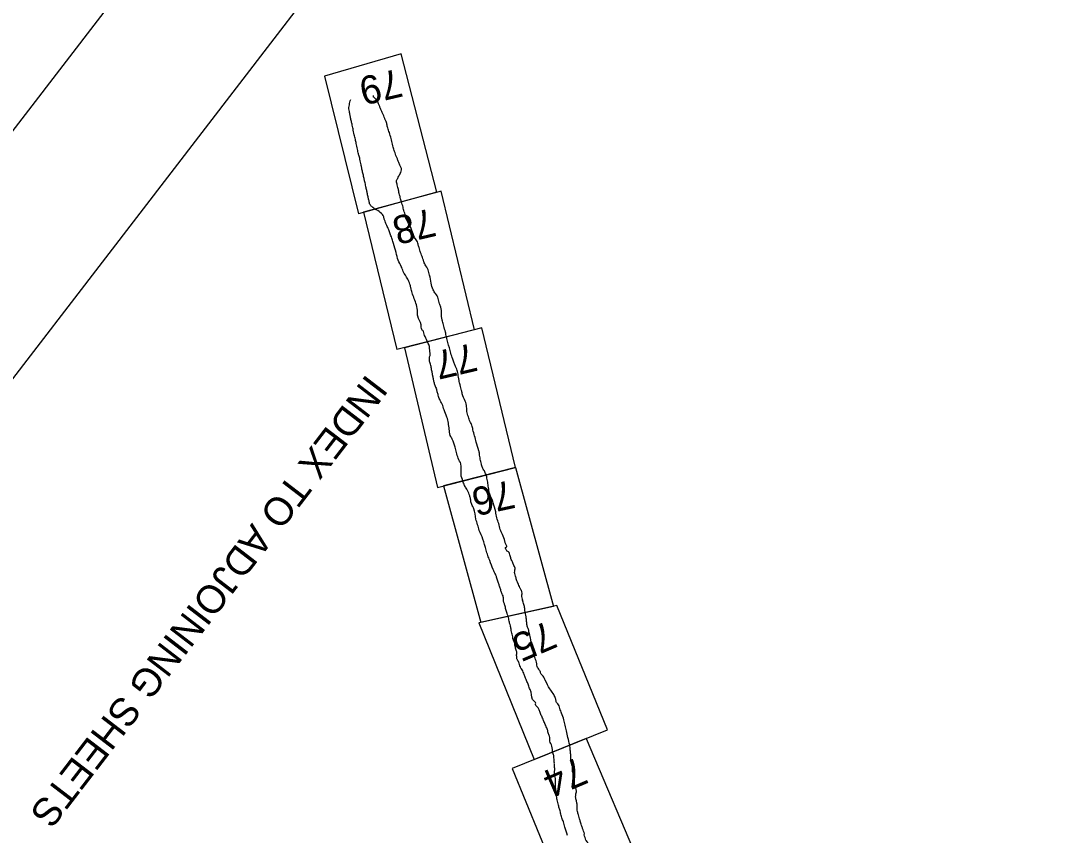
# Model space of a CAD drawing. Extents: x 3879599 to 3900814, y 146526 to 168888.
# Drawn here: x 3883542 to 3885674, y 157470 to 159157 of the extents above; entities that cross this region are included whole.
import ezdxf

# ---------------------------------------------------------------- set-up
doc = ezdxf.new("R2010")
doc.units = 0
for name, color, linetype in [('G-ANNO-NPLT', 7, 'Continuous'), ('V-ANNO-NPLT', 7, 'Continuous'), ('V-ANNO-SYMB', 7, 'Continuous')]:
    doc.layers.add(name, color=color, linetype=linetype)

msp = doc.modelspace()

# ---------------------------------------------------------------- linework, layer by layer
at = {"layer": 'G-ANNO-NPLT'}
msp.add_lwpolyline([(3891001.3, 168656.7), (3879830.2, 154120), (3889411.2, 146757.2), (3900582.4, 161294)], close=True, dxfattribs=at)
at = {"layer": 'V-ANNO-NPLT'}
msp.add_line((3884403.8, 158801.3), (3884241.7, 158756.9), dxfattribs=at)
for points in [[(3884403.8, 158801.3), (3884330.2, 159087.7), (3884171.4, 159041.6), (3884241.7, 158756.9)], [(3884481.9, 158516.7), (3884412.8, 158803.8), (3884252.5, 158759.9)], [(3884252.5, 158759.9), (3884321, 158475.5)], [(3884481.9, 158516.7), (3884321, 158475.5)], [(3884497.4, 158520.7), (3884336.8, 158479.5), (3884405.4, 158190.1)], [(3884566.8, 158231.3), (3884497.4, 158520.7)], [(3884405.4, 158190.1), (3884566.8, 158231.3)], [(3884566.8, 158231.3), (3884418, 158193.3)], [(3884566.8, 158231.3), (3884645.4, 157944)], [(3884418, 158193.3), (3884494.7, 157910.6)], [(3884652.5, 157945.6), (3884490.9, 157909.7), (3884605.6, 157627)], [(3884645.4, 157944), (3884494.7, 157910.6)], [(3884756.9, 157688.5), (3884652.5, 157945.6)], [(3884605.6, 157627), (3884756.9, 157688.5)], [(3884713, 157670.7), (3884559.8, 157608.4), (3884672.7, 157332)], [(3884713, 157670.7), (3884828.5, 157398.7)]]:
    msp.add_lwpolyline(points, dxfattribs=at)
for points in [[(3884228.4, 158942.3), (3884226.7, 158949.8), (3884225.1, 158957.4), (3884223.6, 158964.3), (3884223, 158968.5), (3884222, 158973.7), (3884222.6, 158979.4), (3884223.4, 158985.1), (3884224.8, 158990.3), (3884225.9, 158993.7)], [(3884297.2, 158951.6), (3884292.9, 158962.1), (3884290.1, 158968.3), (3884287.4, 158974.5), (3884285.1, 158980.5), (3884282.6, 158986.2), (3884280.7, 158991.1), (3884279.6, 158992.2), (3884277.4, 158994.3), (3884274.2, 158997.5), (3884273.2, 158998.4), (3884272.8, 158999.7), (3884272.9, 159001.5)], [(3884241.8, 158880.6), (3884239.7, 158890.3), (3884237.2, 158902.5), (3884235.4, 158910.8), (3884233.1, 158920.5), (3884230.5, 158932.6), (3884228.4, 158942.3)], [(3884312.3, 158900.6), (3884309.3, 158912.6), (3884305.7, 158924.9), (3884302.5, 158934.5), (3884300.6, 158942), (3884298.4, 158949.4), (3884297.2, 158951.6)], [(3884329.2, 158842.5), (3884330.6, 158847.9), (3884330.5, 158850.5), (3884328.3, 158855.8), (3884325.3, 158862.7), (3884322.9, 158869), (3884320.2, 158875), (3884318.3, 158879.9), (3884316.6, 158885.8), (3884313.9, 158894.8), (3884312.3, 158900.6)], [(3884257.2, 158813.3), (3884254.8, 158823.2), (3884253.3, 158829.7), (3884251.6, 158838.6), (3884249.4, 158846.8), (3884248.6, 158851.6), (3884247.2, 158858), (3884244.8, 158869.5), (3884242.5, 158878), (3884241.8, 158880.6)], [(3884330.9, 158781.6), (3884329.8, 158785.4), (3884328.3, 158790.5), (3884327.5, 158794.1), (3884326.2, 158798.5), (3884325.2, 158803.8), (3884323.4, 158810.9), (3884322.1, 158816.5), (3884321.2, 158820.3), (3884320.3, 158823.8), (3884323, 158829.9), (3884325.4, 158834.7), (3884327.3, 158838.1), (3884329.2, 158842.5)], [(3884275.5, 158766.6), (3884271.5, 158770), (3884267.3, 158773.5), (3884265.7, 158775.8), (3884263.6, 158783.6), (3884262, 158790), (3884260.3, 158798.4), (3884258.8, 158805.2), (3884257.2, 158812.6), (3884257.2, 158813.3)], [(3884336.6, 158761.1), (3884335.1, 158765.9), (3884334, 158770.6), (3884330.9, 158781.6)], [(3884305.2, 158721.2), (3884301.3, 158730.7), (3884298.6, 158736.6), (3884297.1, 158741.2), (3884294.7, 158747.2), (3884294, 158750.1), (3884275.5, 158766.6)], [(3884389, 158629.7), (3884385.8, 158641), (3884379.8, 158651.3), (3884378, 158654.9), (3884374.3, 158666), (3884370.5, 158676.4), (3884367.2, 158686.8), (3884365, 158693.7), (3884364.2, 158698.6), (3884361.1, 158702.8), (3884351.8, 158724), (3884343.2, 158741), (3884339.2, 158750.4), (3884338.2, 158755.1), (3884336.6, 158761.1)], [(3884348.2, 158611.3), (3884343.8, 158621.2), (3884334.5, 158637.6), (3884330.2, 158647.9), (3884324.2, 158660.4), (3884319.8, 158676.4), (3884314.6, 158695.2), (3884311.7, 158704), (3884308, 158713.4), (3884305.2, 158721.2)], [(3884421.8, 158511.6), (3884418.4, 158524.3), (3884415.5, 158534.6), (3884414, 158541.1), (3884413.4, 158548.6), (3884412.5, 158563.6), (3884409.7, 158570.6), (3884406.8, 158581.4), (3884401.4, 158591.4), (3884396.3, 158599.5), (3884392.4, 158612.8), (3884389, 158629.7)], [(3884385.3, 158490), (3884379.7, 158502.5), (3884377.7, 158507.2), (3884376.5, 158513), (3884372.9, 158517.2), (3884371.5, 158526.7), (3884364.6, 158544.6), (3884364.1, 158553), (3884361.7, 158568.2), (3884352.9, 158593.4), (3884351.7, 158597.9), (3884350.2, 158603.9), (3884348.2, 158611.3)], [(3884445.7, 158435.2), (3884442.6, 158440.7), (3884439.9, 158447.8), (3884437, 158455.9), (3884432.9, 158468), (3884427, 158490), (3884423.9, 158501.7), (3884421.8, 158511.9)], [(3884338.8, 158480.1), (3884338.5, 158479.6), (3884338, 158479.4), (3884337.6, 158479.1), (3884337, 158478.9)], [(3884395.1, 158422.8), (3884395, 158423.8), (3884393.6, 158431.6), (3884392.1, 158440.8), (3884391.1, 158445.1), (3884389.2, 158449.3), (3884389.1, 158456.4), (3884389.1, 158460.9), (3884390, 158463.7), (3884389.7, 158470.6), (3884389.2, 158474.9), (3884388.7, 158482), (3884385.3, 158490)], [(3884505.8, 158217), (3884502.3, 158224.3), (3884498.2, 158231.2), (3884496.1, 158238.7), (3884493.8, 158248.7), (3884492.2, 158259.5), (3884491, 158266.3), (3884485.3, 158284), (3884482.2, 158296.7), (3884478.7, 158309.8), (3884476.5, 158318.9), (3884472.8, 158326.3), (3884469.2, 158336.5), (3884466.3, 158347.6), (3884465.7, 158356.9), (3884462.7, 158368.8), (3884456.5, 158384), (3884456, 158388), (3884455.3, 158390.8), (3884452, 158402.3), (3884450.1, 158411.8), (3884447.8, 158424.6), (3884445.7, 158435.2)], [(3884395.1, 158422.8), (3884396.1, 158415.8), (3884397.7, 158408.7), (3884399.8, 158401.8), (3884403.2, 158394)], [(3884407, 158380.9), (3884405, 158388), (3884403.2, 158394)], [(3884458.1, 158203.5), (3884454.1, 158217.3), (3884453.7, 158238.9), (3884448.3, 158250.5), (3884444.9, 158262.8), (3884442, 158273.9), (3884435.7, 158289.9), (3884431.9, 158298), (3884429.6, 158310.8), (3884427.8, 158323.3), (3884424.8, 158336), (3884419, 158350.8), (3884415.2, 158362.7), (3884409.9, 158372.5), (3884407, 158380.9)], [(3884545, 158078.7), (3884539.6, 158093), (3884535.3, 158103), (3884532.1, 158115.3), (3884528.1, 158127.4), (3884525.8, 158139.7), (3884520.5, 158158.4), (3884518.4, 158164.9), (3884513.9, 158173.4), (3884511.8, 158184), (3884510, 158195.9), (3884508.3, 158206.9), (3884505.8, 158217)], [(3884525.2, 158010.4), (3884520.5, 158020.2), (3884513.4, 158039), (3884509.5, 158049.4), (3884506, 158060.2), (3884499.4, 158083.3), (3884491.9, 158101.3), (3884488.4, 158113.1), (3884484.8, 158124.8), (3884480.6, 158145.9), (3884476.4, 158154.9), (3884474.3, 158162.2), (3884473, 158169.7), (3884471, 158175.4), (3884466.1, 158186.5), (3884461.2, 158194.5), (3884458.1, 158203.5)], [(3884555.6, 158048.5), (3884552.1, 158056.7), (3884549.4, 158058.1), (3884548.6, 158058.9), (3884547.4, 158061.3), (3884546.6, 158063.3), (3884546.1, 158065), (3884546.2, 158065.6), (3884548.7, 158067.1), (3884549, 158067.7), (3884546.7, 158072.5), (3884544.8, 158078.4)], [(3884578.5, 157977.4), (3884576.1, 157982.7), (3884571.9, 157992.1), (3884569, 157998.9), (3884566.8, 158006.7), (3884565.3, 158011.8), (3884565.1, 158017.1), (3884565.8, 158021.5), (3884565.4, 158025.2), (3884563.5, 158028.4), (3884560.4, 158036.4), (3884557.9, 158041.3), (3884556.9, 158044.5), (3884555.6, 158048.5)], [(3884559.9, 157886.2), (3884557.6, 157896.7), (3884556.2, 157903.9), (3884554.7, 157909), (3884552.7, 157918.4), (3884549.6, 157929.2), (3884546.8, 157937.6), (3884544.9, 157946.4), (3884542.7, 157952), (3884541.9, 157958.7), (3884541.6, 157964), (3884538.4, 157971), (3884536.3, 157978.2), (3884533.9, 157985.7), (3884531.6, 157992), (3884529.1, 158000.6), (3884527.8, 158004.4), (3884525.2, 158010.4)], [(3884578.5, 157977.4), (3884579.8, 157971.2), (3884579.5, 157967), (3884579.9, 157961.8), (3884581.4, 157956.7)], [(3884589, 157922.2), (3884586.4, 157935.5), (3884585.1, 157943.7), (3884582.6, 157952.4), (3884581.4, 157956.7)], [(3884628.4, 157790.9), (3884625.1, 157797.7), (3884620.2, 157803.8), (3884617.6, 157809.5), (3884613.7, 157815.7), (3884611.3, 157819.4), (3884610.8, 157825.5), (3884610.2, 157828.7), (3884606.3, 157839.4), (3884603.9, 157849.3), (3884603.1, 157854.4), (3884601.2, 157860.9), (3884599.2, 157869.6), (3884598.3, 157875.2), (3884595.7, 157887.5), (3884594.5, 157891.1), (3884594.3, 157894.8), (3884591.4, 157901.1), (3884590.4, 157908.2), (3884589.3, 157917.5), (3884589, 157922.2)], [(3884599.5, 157766.1), (3884596.1, 157774.1), (3884592.9, 157782.9), (3884589.8, 157790.3), (3884587.7, 157795.5), (3884584.9, 157803.1), (3884580.4, 157812.5), (3884578, 157816.2), (3884575.9, 157820.9), (3884574.4, 157826.2), (3884570.9, 157833), (3884569.8, 157835.6), (3884569.3, 157840), (3884568.9, 157843.9), (3884569.8, 157847.2), (3884568.1, 157853), (3884566.9, 157857.5), (3884565.4, 157865.8), (3884564.7, 157869.9), (3884562.5, 157873.9), (3884561, 157880.9), (3884559.9, 157886.2)], [(3884679, 157657), (3884675.3, 157672.5), (3884672.5, 157686), (3884669.5, 157697.8), (3884666.9, 157709.4), (3884662.1, 157722.6), (3884658.7, 157732.4), (3884654.3, 157742.5), (3884651.6, 157745.1), (3884650.3, 157751.6), (3884649.2, 157755.4), (3884644.6, 157763.7), (3884638, 157773.2), (3884628.4, 157790.9)], [(3884647.4, 157619.7), (3884646.5, 157627.5), (3884646.2, 157633.1), (3884644.1, 157640.7), (3884642.1, 157654.6), (3884638, 157665), (3884637.2, 157675.1), (3884634.4, 157682.1), (3884633.6, 157686.9), (3884632.6, 157690.1), (3884628.2, 157699.4), (3884624.9, 157708), (3884621, 157716.4), (3884617.8, 157724.3), (3884615.1, 157731.2), (3884611.2, 157736.7), (3884608.1, 157740.9), (3884608.7, 157743.9), (3884607.8, 157745.8), (3884604.9, 157748.1), (3884599.5, 157766.1)], [(3884700, 157501.8), (3884696.9, 157512.1), (3884695.2, 157519.1), (3884694.2, 157525.5), (3884694.1, 157534.6), (3884692.7, 157541.3), (3884691.2, 157549.3), (3884692, 157555.9), (3884692.6, 157563.8), (3884690, 157570.4), (3884688.8, 157580.9), (3884687.2, 157590.1), (3884686.9, 157598.2), (3884684.9, 157602), (3884684.8, 157608.2), (3884681.8, 157623.5), (3884681.2, 157634.7), (3884680.4, 157644.3), (3884679.6, 157651.7), (3884679, 157657)], [(3884674.3, 157469.8), (3884669.1, 157487.1), (3884666, 157498), (3884662.6, 157506.4), (3884660.2, 157516.1), (3884658, 157524.6), (3884655.6, 157532.1), (3884654.3, 157538.2), (3884652.2, 157548.3), (3884650.7, 157561.3), (3884649.3, 157577.1), (3884649.3, 157587.7), (3884647.8, 157598.5), (3884647.9, 157605.7), (3884647.5, 157615), (3884647.4, 157618.4)], [(3884752.8, 157387.7), (3884749.7, 157393.1), (3884746.5, 157398.9), (3884741.5, 157406.1), (3884737.8, 157413.7), (3884733.9, 157422.9), (3884731.6, 157427.5), (3884729, 157432.4), (3884723.7, 157438), (3884720.2, 157445.9), (3884717.1, 157452.6), (3884715.3, 157456.8), (3884712.4, 157460.1), (3884710.7, 157465.6), (3884708.8, 157470.8), (3884709.3, 157473.2), (3884707.7, 157478.7), (3884705.8, 157483.9), (3884703.5, 157490.4), (3884702.2, 157495.2), (3884700.9, 157499.4), (3884700, 157501.8)]]:
    msp.add_spline(points, degree=3, dxfattribs=at)
at = {"layer": 'V-ANNO-SYMB'}
msp.add_lwpolyline([(3890411.2, 167376), (3880331.9, 154259.9), (3889417.3, 147278), (3899496.7, 160394.1), (3890411.2, 167376)], dxfattribs=at)

# ---------------------------------------------------------------- texts
at = {"layer": 'V-ANNO-NPLT'}
for s, height, rotation, p in [('79', 58.5, 193.1706, (3884323.8, 159057.5)), ('78', 58.5, 193.1706, (3884393.1, 158768.8)), ('77', 58.5, 193.1706, (3884478.8, 158489.8)), ('INDEX TO ADJOINING SHEETS', 58.33, 232.4587, (3884259.4, 158427)), ('76', 58.5, 192.1706, (3884557.6, 158205.9)), ('75', 58.5, 203.1706, (3884634.4, 157915.5)), ('74', 58.5, 203.1706, (3884698.1, 157634))]:
    msp.add_text(s, height=height, rotation=rotation, dxfattribs=at).set_placement(p)

doc.saveas('drawing.dxf')
